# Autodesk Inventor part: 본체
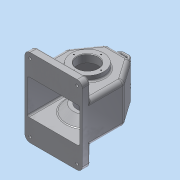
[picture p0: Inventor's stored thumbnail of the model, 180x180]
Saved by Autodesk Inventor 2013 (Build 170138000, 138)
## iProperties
Created: 2016-12
Part Number: 본체
Material: 알루미늄 6061
Document SubType Name: Modeling
Designer: dgall
Density: 2.71 g/cm^3
Mass: 1067.34 g
Surface Area: 1137.96 cm^2
Volume: 393.853 cm^3
Author: dgall
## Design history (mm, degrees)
sketch "스케치1"
  geometry: L1 (-55, 0)-(-55, 80); L2 (-55, 80)-(-23.491, 125); L3 (-23.491, 125)-(23.491, 125); L4 (23.491, 125)-(55, 80); L5 (55, 80)-(55, 0); L6 (55, 0)-(-55, 0); 2 further points
  constraints: 12 end point, 1 coincident, 1 horizontal alignment, 1 midpoint, 1 parallel, 1 perpendicular, 1 vertical
  dimensions: "d0" = 35 deg angle of L2 L1; "d1" = 35 deg angle of L4 L5; "d3" = 125 distance between parallel lines of L6 L3; "d5" = 80 distance of L4.end L5.end; "d6" = 110 distance of L5.end L1.start
extrude "돌출1" new body sketch "스케치1" distance "d7" = 77; taper "d8" = 0 deg
feature "쉘1" dims "d9" = 5
node "작업 평면1"
sketch "스케치3"
  geometry: L1 (5, 5)-(5, 72) reference; L2 (110, 0)-(0, 0) reference; L3 (110, 0)-(110, 77) reference; L4 (0, 77)-(110, 77) reference; L5 (0, 0)-(0, 77) reference; L6 (0, 113.5)-(110, 113.5); L7 (110, 113.5)-(110, -36.5); L8 (110, -36.5)-(0, -36.5); L9 (0, -36.5)-(0, 113.5); 3 further points
  constraints: 8 end point, 2 midpoint, 2 parallel, 2 vertical alignment, 1 horizontal, 1 horizontal alignment, 1 perpendicular
  dimensions: "d27" = 150 distance of L6.end L7.end
extrude "돌출2" join sketch "스케치3" distance "d29" = 15; taper "d30" = 0 deg
node "작업 평면2"
fillet "모깎기1" dims "d43" = 10
hole "구멍1" diameter "d46" = 5; stored, may be unused: countersink angle "d50" = 90 deg, drill point angle "d52" = 118 deg; dims "d44" = 10, "d45" = 10, "d47" = 6, "d48" = 12, "d49" = 5, "d51" = 8
node "작업 평면3"
sketch "스케치5"
  geometry: C1 r 37.5 at (0, 65); 1 further point
  constraints: 1 centre point, 1 vertical alignment
  dimensions: "d53" = 65 distance of point (0, 0) C1.centre; "d54" = 75 diameter of C1
extrude "돌출3" join sketch "스케치5" distance "d55" = 5; taper "d56" = 0 deg
node "작업 평면4"
sketch "스케치6"
  geometry: L1 (72, 40)-(5, 40) reference; L2 (5, 40)-(5, -80) reference; L3 (5, -80)-(-36.5, -80) reference; L4 (-36.5, -80)-(-36.5, -65) reference; L5 (-36.5, -65)-(0, -65) reference; L6 (0, -65)-(0, -52.5) reference; L7 (0, -52.5)-(-5, -52.5) reference; L8 (-5, -52.5)-(-5, 22.5) reference; L9 (-5, 22.5)-(0, 22.5) reference; L10 (0, 22.5)-(0, 45) reference; L11 (0, 45)-(77, 45) reference; L12 (77, 45)-(77, -65) reference; L13 (77, -65)-(113.5, -65) reference; L14 (113.5, -65)-(113.5, -80) reference; L15 (113.5, -80)-(72, -80) reference; L16 (72, -80)-(72, 40) reference; L17 (-5, -15)-(19, -15); L18 (19, -15)-(19, 12); L19 (19, 12)-(5, 26); L20 (5, 26)-(5, -15); 1 further point
  constraints: 8 end point, 3 point on line, 2 perpendicular, 1 midpoint
  dimensions: "d57" = 24 distance of L17.start L17.end; "d59" = 54 diameter of L18.end L17; "d60" = 45 deg angle of L19 L18
revolve "회전1" sketch "스케치6" stored, may be unused: angle "d61" = 90 deg
sketch "스케치7"
  geometry: C1 r 31 at (0, 65); 1 further point
  constraints: 1 centre point, 1 vertical alignment
  dimensions: "d62" = 65 distance of C1.centre point (0, 0); "d63" = 62 diameter of C1
extrude "돌출4" join sketch "스케치7" distance "d64" = 10; taper "d65" = 0 deg
hole "구멍2" diameter "d68" = 40; stored, may be unused: countersink angle "d72" = 90 deg, drill point angle "d74" = 0 deg; dims "d66" = 10, "d67" = 10, "d69" = 6, "d70" = 12, "d71" = 5, "d73" = 15
hole "구멍3" diameter "d77" = 40; stored, may be unused: countersink angle "d81" = 90 deg, drill point angle "d83" = 0 deg; dims "d75" = 10, "d76" = 10, "d78" = 6, "d79" = 12, "d80" = 5, "d82" = 24
chamfer "모따기1" distance "d84" = 1; stored, may be unused: second distance "d85" = 2, angle "d86" = 45 deg
sketch "스케치8"
  geometry: C1 r 37.5 at (0, 0) reference; 2 further points
  constraints: 1 vertical alignment
  dimensions: "d87" = 29 distance of C1.centre point (0, 29)
hole "구멍4" sketch "스케치8" at (0, 29) diameter "d88" = 2.459; stored, may be unused: countersink angle "d92" = 90 deg, drill point angle "d94" = 118 deg; dims "d89" = 6, "d90" = 12, "d91" = 5, "d93" = 8
sketch "스케치9"
  geometry: C1 r 31 at (0, 0) reference; 2 further points
  constraints: 1 vertical alignment
  dimensions: "d98" = 26 distance of C1.centre point (0, 26)
hole "구멍5" sketch "스케치9" at (0, 26) diameter "d99" = 2.459; stored, may be unused: countersink angle "d103" = 90 deg, drill point angle "d105" = 118 deg; dims "d100" = 6, "d101" = 12, "d102" = 5, "d104" = 8
fillet "모깎기2" dims "d109" = 3
fillet "모깎기3" dims "d110" = 10
fillet "모깎기4" dims "d111" = 10
fillet "모깎기5" dims "d112" = 8
fillet "모깎기6" dims "d113" = 3
fillet "모깎기7" dims "d114" = 3
fillet "모깎기8" dims "d115" = 5
fillet "모깎기9" dims "d116" = 3
fillet "모깎기10" dims "d117" = 3
node "작업 평면6"
  node "작업 평면5"
sketch "스케치10"
  geometry: L1 (-55, 0)-(-55, 76.847) reference; L2 (-53.192, 82.583)-(-26.477, 120.736) reference; L3 (-18.285, 125)-(18.285, 125) reference; L4 (26.477, 120.736)-(53.192, 82.583) reference; L5 (55, 76.847)-(55, 0) reference; L6 (55, 0)-(50, 0) reference; L7 (50, 0)-(50, 76.847) reference; L8 (49.096, 79.715)-(22.381, 117.868) reference; L9 (18.285, 120)-(-18.285, 120) reference; L10 (-22.381, 117.868)-(-49.096, 79.715) reference; L11 (-50, 76.847)-(-50, 0) reference; L12 (-50, 0)-(-55, 0) reference; L13 (-12.5, 125)-(-12.5, 140); L14 (-12.5, 140)-(12.5, 140); L15 (12.5, 140)-(12.5, 125); L16 (-7.5, 125)-(-7.5, 135); L17 (-7.5, 135)-(7.5, 135); L18 (7.5, 135)-(7.5, 125); A1 r 10 centre (-45, 76.847) between (-53.192, 82.583) and (-55, 76.847) reference; A2 r 10 centre (-18.285, 115) between (-18.285, 125) and (-26.477, 120.736) reference; A3 r 10 centre (18.285, 115) between (26.477, 120.736) and (18.285, 125) reference; A4 r 10 centre (45, 76.847) between (55, 76.847) and (53.192, 82.583) reference; A5 r 5 centre (45, 76.847) between (50, 76.847) and (49.096, 79.715) reference; A6 r 5 centre (18.285, 115) between (22.381, 117.868) and (18.285, 120) reference; A7 r 5 centre (-18.285, 115) between (-18.285, 120) and (-22.381, 117.868) reference; A8 r 5 centre (-45, 76.847) between (-49.096, 79.715) and (-50, 76.847) reference; 4 further points
  constraints: 12 end point, 5 perpendicular, 4 point on line, 3 midpoint, 2 vertical alignment, 1 parallel
  dimensions: "d119" = 25 distance of L13.end L14.end; "d120" = 15 distance of L16.end L17.end; "d121" = 140 distance between parallel lines of L14 L6; "d123" = 5 distance between parallel lines of L17 L14
extrude "돌출5" join sketch "스케치10" distance "d124" = 8; taper "d125" = 0 deg
fillet "모깎기11" dims "d126" = 8
fillet "모깎기12" dims "d127" = 1
fillet "모깎기13" dims "d128" = 3
fillet "모깎기14" dims "d129" = 1
fillet "모깎기15" dims "d130" = 1
node "작업 평면8"
  node "작업 평면7"
sketch "스케치11"
  geometry: L1 (-55, 0)-(-55, 76.847) reference; L2 (-53.192, 82.583)-(-26.477, 120.736) reference; L3 (-18.285, 125)-(18.285, 125) reference; L4 (26.477, 120.736)-(53.192, 82.583) reference; L5 (55, 76.847)-(55, 0) reference; L6 (55, 0)-(50, 0) reference; L7 (50, 0)-(50, 76.847) reference; L8 (49.096, 79.715)-(22.381, 117.868) reference; L9 (18.285, 120)-(-18.285, 120) reference; L10 (-22.381, 117.868)-(-49.096, 79.715) reference; L11 (-50, 76.847)-(-50, 0) reference; L12 (-50, 0)-(-55, 0) reference; L13 (-12.5, 125)-(-12.5, 140); L14 (-12.5, 140)-(12.5, 140); L15 (12.5, 140)-(12.5, 125); L16 (-7.5, 125)-(-7.5, 135); L17 (-7.5, 135)-(7.5, 135); L18 (7.5, 135)-(7.5, 125); A1 r 10 centre (-45, 76.847) between (-53.192, 82.583) and (-55, 76.847) reference; A2 r 10 centre (-18.285, 115) between (-18.285, 125) and (-26.477, 120.736) reference; A3 r 10 centre (18.285, 115) between (26.477, 120.736) and (18.285, 125) reference; A4 r 10 centre (45, 76.847) between (55, 76.847) and (53.192, 82.583) reference; A5 r 5 centre (45, 76.847) between (50, 76.847) and (49.096, 79.715) reference; A6 r 5 centre (18.285, 115) between (22.381, 117.868) and (18.285, 120) reference; A7 r 5 centre (-18.285, 115) between (-18.285, 120) and (-22.381, 117.868) reference; A8 r 5 centre (-45, 76.847) between (-49.096, 79.715) and (-50, 76.847) reference; 4 further points
  constraints: 12 end point, 5 perpendicular, 4 point on line, 3 midpoint, 2 vertical alignment, 1 parallel
  dimensions: "d132" = 25 distance of L13.end L14.end; "d133" = 15 distance of L16.end L17.end; "d134" = 140 distance from line of L5.end L14; "d135" = 5 distance between parallel lines of L17 L14
extrude "돌출6" join sketch "스케치11" distance "d136" = 8; taper "d137" = 0 deg
fillet "모깎기16" dims "d138" = 8
fillet "모깎기17" dims "d139" = 3
fillet "모깎기18" dims "d140" = 1
fillet "모깎기19" dims "d141" = 1
fillet "모깎기20" dims "d142" = 1
sketch "스케치12"
  geometry: L1 (34.5, 76.847)-(95.5, 76.847) reference; L2 (0, 0)-(130, 0) reference; L3 (26.5, 76.847)-(26.5, 18) reference; L4 (95.5, 76.847)-(34.5, 76.847) reference; 4 further points
  constraints: 2 midpoint, 1 coincident, 1 other
  dimensions: "d143" = 38.5 distance from line of point (65, 45) L3; "d144" = 45 distance from line of point (65, 45) L2
feature "엠보싱1" sketch "스케치12" dims "d3" = 125, "d145" = 0.5, "d146" = 0
node "솔리드1"
mirror "대칭1"
mirror "대칭2"
pattern_circular "원형 패턴1" dims angle "d96" = 360 deg
pattern_circular "원형 패턴2" dims angle "d107" = 360 deg
node "절단 모서리 투영3"
node "절단 모서리 투영4"
node "절단 모서리 투영5"
other parameters: "d13" = 54, "d14" = 75, "d118" = 26, "d131" = -18
